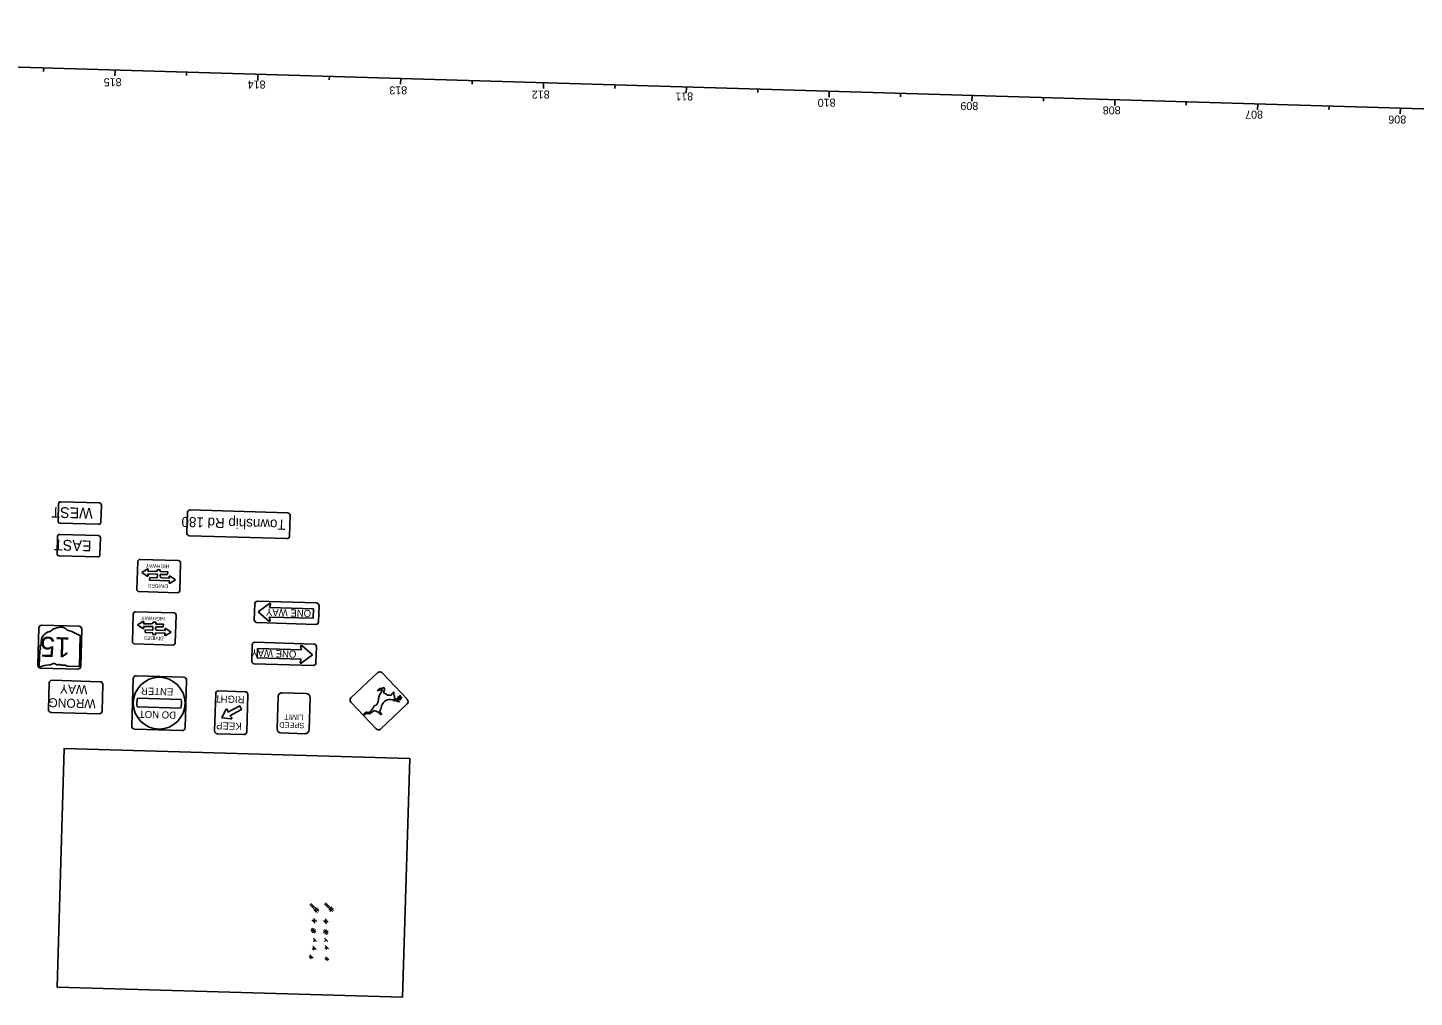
# Model space of a CAD drawing. Extents: x 1658454 to 1663955, y 480219 to 484109.
# Drawn here: x 1659392 to 1660362, y 482120 to 482799 of the extents above; entities that cross this region are included whole.
import ezdxf

# ---------------------------------------------------------------- set-up
doc = ezdxf.new("R2010")
doc.units = 0
for name, color, linetype in [('Default', 7, 'Continuous'), ('SN_P_Signs', 7, 'Continuous'), ('SN_X_Public', 7, 'Continuous'), ('SV_X_CL_Survey_50', 7, 'Continuous'), ('SV_X_Text', 7, 'Continuous')]:
    doc.layers.add(name, color=color, linetype=linetype)

msp = doc.modelspace()

# ---------------------------------------------------------------- linework, layer by layer
at = {"layer": 'Default'}
for p, q in [((1659403.25, 482770.68), (1659403.18, 482768.28)), ((1659453.23, 482769.19), (1659453.11, 482765.19)), ((1659503.2, 482767.71), (1659503.13, 482765.31)), ((1659553.18, 482766.23), (1659553.06, 482762.23)), ((1659603.16, 482764.74), (1659603.09, 482762.34)), ((1659653.14, 482763.26), (1659653.02, 482759.26)), ((1659703.12, 482761.77), (1659703.04, 482759.37)), ((1659753.09, 482760.29), (1659752.97, 482756.29)), ((1659803.07, 482758.81), (1659803, 482756.41)), ((1659853.05, 482757.32), (1659852.93, 482753.32)), ((1659903.03, 482755.84), (1659902.96, 482753.44)), ((1659953.01, 482754.35), (1659952.89, 482750.36)), ((1660002.98, 482752.87), (1660002.91, 482750.47)), ((1660052.96, 482751.39), (1660052.84, 482747.39)), ((1660102.94, 482749.9), (1660102.87, 482747.5)), ((1660152.92, 482748.42), (1660152.8, 482744.42)), ((1660202.89, 482746.93), (1660202.82, 482744.54)), ((1660252.87, 482745.45), (1660252.75, 482741.45)), ((1660302.85, 482743.97), (1660302.78, 482741.57)), ((1660352.83, 482742.48), (1660352.71, 482738.48))]:
    msp.add_line(p, q, dxfattribs=at)
at = {"layer": 'SN_P_Signs'}
for p, q in [((1659594.96, 482179.5), (1659589.53, 482184.93)), ((1659595.67, 482180.21), (1659590.23, 482185.64)), ((1659591.59, 482184.28), (1659590.89, 482183.57)), ((1659594.66, 482182.76), (1659592.4, 482180.5)), ((1659592.6, 482182.57), (1659592.6, 482182.57)), ((1659595.51, 482181.92), (1659593.25, 482179.65)), ((1659593.16, 482171.88), (1659590.89, 482174.15)), ((1659591.68, 482173.36), (1659592.82, 482174.49)), ((1659594.29, 482173.02), (1659592.02, 482175.28)), ((1659592.36, 482172.68), (1659593.5, 482173.81)), ((1659592.59, 482173.58), (1659592.59, 482173.58)), ((1659592.89, 482164.99), (1659590.17, 482167.7)), ((1659592.59, 482168.25), (1659590.33, 482165.99)), ((1659593.6, 482165.69), (1659590.88, 482168.41)), ((1659593.44, 482167.4), (1659591.18, 482165.14)), ((1659591.88, 482166.7), (1659591.88, 482166.7)), ((1659592.35, 482154.96), (1659591.22, 482153.83)), ((1659591.56, 482155.75), (1659593.82, 482153.49)), ((1659593.03, 482154.28), (1659591.9, 482153.15)), ((1659591.94, 482161.42), (1659594.2, 482159.16)), ((1659593.07, 482160.29), (1659591.94, 482159.16)), ((1659592.69, 482154.62), (1659592.69, 482154.62)), ((1659592.69, 482154.62), (1659592.69, 482154.62)), ((1659590.17, 482149.17), (1659589.04, 482148.04)), ((1659589.55, 482149.79), (1659591.81, 482147.53)), ((1659590.68, 482148.66), (1659589.55, 482147.53)), ((1659591.19, 482148.15), (1659590.06, 482147.02))]:
    msp.add_line(p, q, dxfattribs=at)
at = {"layer": 'SN_X_Public'}
for p, q in [((1659413.24, 482453.53), (1659413.59, 482465.52)), ((1659415.14, 482466.97), (1659442.12, 482466.17)), ((1659443.58, 482464.63), (1659443.22, 482452.63)), ((1659503.34, 482445.2), (1659503.76, 482459.36)), ((1659505.74, 482461.22), (1659573.87, 482459.2)), ((1659575.74, 482457.22), (1659575.31, 482443.07)), ((1659414.46, 482444.14), (1659441.45, 482443.34)), ((1659441.68, 482451.18), (1659414.69, 482451.98)), ((1659412.56, 482430.69), (1659412.91, 482442.69)), ((1659442.9, 482441.8), (1659442.54, 482429.8)), ((1659573.34, 482441.2), (1659505.2, 482443.23)), ((1659441, 482428.35), (1659414.01, 482429.15)), ((1659468.98, 482425.13), (1659468.41, 482405.64)), ((1659497.52, 482425.78), (1659470.53, 482426.58)), ((1659498.39, 482404.75), (1659498.97, 482424.24)), ((1659475.73, 482419.83), (1659471.89, 482417.47)), ((1659471.89, 482417.47), (1659475.59, 482414.88)), ((1659476.3, 482415.36), (1659476.03, 482416.41)), ((1659476.03, 482416.41), (1659482.79, 482416.21)), ((1659476.1, 482418.28), (1659476.42, 482419.31)), ((1659481.6, 482418.12), (1659476.1, 482418.28)), ((1659482.79, 482416.21), (1659482.71, 482413.71)), ((1659484.76, 482419.28), (1659482.88, 482419.33)), ((1659482.88, 482419.33), (1659482.88, 482419.33)), ((1659484.63, 482414.9), (1659484.66, 482416.15)), ((1659484.66, 482416.15), (1659489.97, 482416)), ((1659484.72, 482418.03), (1659484.76, 482419.28)), ((1659490.03, 482417.87), (1659484.72, 482418.03)), ((1659489.97, 482416), (1659490.03, 482417.87)), ((1659491.1, 482414.5), (1659491.35, 482413.45)), ((1659495.49, 482412.39), (1659491.79, 482414.98)), ((1659477.41, 482413.87), (1659477.35, 482411.99)), ((1659477.35, 482411.99), (1659491.3, 482411.58)), ((1659482.71, 482413.71), (1659477.41, 482413.87)), ((1659491.35, 482413.45), (1659485.84, 482413.62)), ((1659491.3, 482411.58), (1659490.99, 482410.57)), ((1659491.65, 482410.03), (1659495.49, 482412.39)), ((1659491.65, 482410.04), (1659491.65, 482410.03)), ((1659469.86, 482404.09), (1659496.85, 482403.29)), ((1659553.27, 482389.81), (1659561.25, 482395.72)), ((1659561.98, 482395.21), (1659561.29, 482392.84)), ((1659465.33, 482368.97), (1659465.91, 482388.46)), ((1659467.45, 482389.91), (1659494.44, 482389.11)), ((1659495.9, 482387.57), (1659495.32, 482368.08)), ((1659560.88, 482383.41), (1659553.27, 482389.81)), ((1659591.92, 482385.37), (1659561.1, 482386.28)), ((1659561.1, 482386.28), (1659561.65, 482383.87)), ((1659561.29, 482392.84), (1659592.11, 482391.93)), ((1659592.11, 482391.93), (1659591.92, 482385.37)), ((1659472.66, 482383.16), (1659468.81, 482380.8)), ((1659468.81, 482380.8), (1659472.51, 482378.22)), ((1659473.23, 482378.69), (1659472.96, 482379.74)), ((1659472.96, 482379.74), (1659479.71, 482379.54)), ((1659473.02, 482381.61), (1659473.34, 482382.64)), ((1659478.52, 482381.45), (1659473.02, 482381.61)), ((1659474.33, 482377.2), (1659474.28, 482375.32)), ((1659479.64, 482377.04), (1659474.33, 482377.2)), ((1659479.71, 482379.54), (1659479.64, 482377.04)), ((1659481.68, 482382.61), (1659479.81, 482382.66)), ((1659479.81, 482382.66), (1659479.81, 482382.66)), ((1659481.55, 482378.23), (1659481.59, 482379.48)), ((1659481.59, 482379.48), (1659486.9, 482379.33)), ((1659481.64, 482381.36), (1659481.68, 482382.61)), ((1659486.95, 482381.2), (1659481.64, 482381.36)), ((1659488.28, 482376.78), (1659482.76, 482376.95)), ((1659486.9, 482379.33), (1659486.95, 482381.2)), ((1659488.03, 482377.83), (1659488.28, 482376.78)), ((1659488.57, 482373.36), (1659492.42, 482375.72)), ((1659492.42, 482375.72), (1659488.72, 482378.31)), ((1659428.19, 482351.9), (1659428.83, 482373.24)), ((1659493.77, 482366.62), (1659466.79, 482367.42)), ((1659474.28, 482375.32), (1659479.58, 482375.16)), ((1659479.58, 482375.16), (1659479.55, 482373.92)), ((1659479.55, 482373.92), (1659481.42, 482373.86)), ((1659481.42, 482373.86), (1659481.46, 482375.11)), ((1659481.46, 482375.11), (1659488.23, 482374.91)), ((1659488.23, 482374.91), (1659487.91, 482373.9)), ((1659488.58, 482373.37), (1659488.57, 482373.36)), ((1659583.06, 482365.78), (1659583.6, 482363.37)), ((1659591.43, 482359.86), (1659583.82, 482366.24)), ((1659400.39, 482363), (1659400.06, 482351.84)), ((1659400.39, 482363), (1659400.39, 482363)), ((1659552.78, 482364.28), (1659552.59, 482357.72)), ((1659552.59, 482357.72), (1659583.41, 482356.81)), ((1659583.6, 482363.37), (1659552.78, 482364.28)), ((1659583.41, 482356.81), (1659582.72, 482354.43)), ((1659583.45, 482353.92), (1659591.43, 482359.86)), ((1659419.67, 482351.79), (1659427.91, 482351.54)), ((1659468.82, 482329.53), (1659499.42, 482328.62)), ((1659647.76, 482328.4), (1659646, 482328.54)), ((1659646.01, 482331.45), (1659646.72, 482331.65)), ((1659499.24, 482322.38), (1659468.63, 482323.29)), ((1659527.86, 482315.71), (1659530.77, 482321.51)), ((1659531.79, 482321.37), (1659532.13, 482319.61)), ((1659532.13, 482319.61), (1659540.4, 482324.06)), ((1659541.73, 482321.58), (1659533.46, 482317.13)), ((1659540.4, 482324.06), (1659541.73, 482321.58)), ((1659534.3, 482314.95), (1659527.86, 482315.71)), ((1659533.46, 482317.13), (1659534.75, 482315.88)), ((1659605.23, 482180), (1659599.8, 482185.43)), ((1659605.94, 482180.71), (1659600.51, 482186.14)), ((1659601.86, 482184.78), (1659601.16, 482184.07)), ((1659604.93, 482183.27), (1659602.67, 482181)), ((1659602.87, 482183.07), (1659602.87, 482183.07)), ((1659605.78, 482182.42), (1659603.52, 482180.15)), ((1659601.23, 482171.51), (1659598.97, 482173.77)), ((1659599.76, 482172.98), (1659600.89, 482174.11)), ((1659602.36, 482172.64), (1659600.1, 482174.9)), ((1659600.44, 482172.3), (1659601.57, 482173.43)), ((1659600.66, 482173.21), (1659600.66, 482173.21)), ((1659601.69, 482164.08), (1659598.98, 482166.79)), ((1659601.39, 482167.34), (1659599.13, 482165.08)), ((1659602.4, 482164.78), (1659599.68, 482167.5)), ((1659602.24, 482166.5), (1659599.98, 482164.23)), ((1659600.69, 482165.79), (1659600.69, 482165.79)), ((1659599.79, 482161.32), (1659602.06, 482159.06)), ((1659600.93, 482160.19), (1659599.79, 482159.06)), ((1659601.08, 482155.39), (1659599.95, 482154.26)), ((1659600.29, 482156.18), (1659602.55, 482153.92)), ((1659601.76, 482154.71), (1659600.63, 482153.58)), ((1659601.42, 482155.05), (1659601.42, 482155.05)), ((1659601.19, 482147.82), (1659600.06, 482146.69)), ((1659600.57, 482148.44), (1659602.83, 482146.18)), ((1659601.7, 482147.31), (1659600.57, 482146.18)), ((1659602.21, 482146.8), (1659601.08, 482145.67))]:
    msp.add_line(p, q, dxfattribs=at)
for points in [[(1659550.95, 482395.49), (1659550.62, 482384.25)], [(1659594.11, 482396.09), (1659552.88, 482397.31)], [(1659595.6, 482382.91), (1659595.93, 482394.16)], [(1659399.89, 482378.72), (1659399.12, 482352.48)], [(1659428.06, 482379.76), (1659401.82, 482380.54)], [(1659429.1, 482351.59), (1659429.88, 482377.83)], [(1659552.44, 482382.32), (1659593.67, 482381.09)], [(1659548.77, 482355.49), (1659549.1, 482366.74)], [(1659551.03, 482368.56), (1659592.27, 482367.33)], [(1659594.09, 482365.4), (1659593.75, 482354.16)], [(1659400.93, 482350.55), (1659427.17, 482349.77)], [(1659591.82, 482352.34), (1659550.59, 482353.56)], [(1659618.28, 482329.65), (1659637.06, 482347.34)], [(1659640.03, 482347.26), (1659657.72, 482328.48)], [(1659407.11, 482340.15), (1659406.55, 482321.41)], [(1659442.78, 482340.97), (1659409.04, 482341.97)], [(1659444.04, 482320.3), (1659444.59, 482339.04)], [(1659465.77, 482342.91), (1659464.8, 482310.11)], [(1659500.98, 482344.21), (1659468.18, 482345.18)], [(1659502.28, 482309), (1659503.25, 482341.8)], [(1659637.59, 482334.51), (1659636.78, 482334.71), (1659636.97, 482335.09), (1659638.33, 482336.18), (1659639.76, 482336.13), (1659640.85, 482336.77)], [(1659522.83, 482306.48), (1659523.61, 482332.72)], [(1659525.54, 482334.54), (1659544.28, 482333.98)], [(1659546.1, 482332.05), (1659545.32, 482305.81)], [(1659567.23, 482330.49), (1659566.56, 482308)], [(1659586.99, 482332.71), (1659570.12, 482333.22)], [(1659589.05, 482307.33), (1659589.72, 482329.82)], [(1659639.86, 482335.25), (1659639.38, 482335.2), (1659638.69, 482335.18)], [(1659641.51, 482332.9), (1659642.66, 482332.52), (1659643.93, 482331.64)], [(1659648.63, 482327.43), (1659648.49, 482327.62), (1659647.68, 482328.14), (1659647.76, 482328.4), (1659647.76, 482328.4)], [(1659408.37, 482319.48), (1659442.11, 482318.48)], [(1659635.89, 482307.9), (1659618.19, 482326.68)], [(1659631.05, 482318.6), (1659628.55, 482318.67), (1659628.22, 482317.99), (1659627.28, 482318.02), (1659628.26, 482319.19)], [(1659657.63, 482325.51), (1659638.86, 482307.82)], [(1659467.07, 482307.7), (1659499.87, 482306.73)], [(1659543.39, 482304), (1659524.65, 482304.55)], [(1659569.29, 482305.1), (1659586.15, 482304.6)]]:
    msp.add_lwpolyline(points, dxfattribs=at)
msp.add_circle((1659484.03, 482325.95), 18.12, dxfattribs=at)
for centre, radius, start, end in [((1659415.09, 482465.48), 1.5, 88.29934, 178.29934), ((1659442.08, 482464.67), 1.5, 358.29934, 88.29934), ((1659414.74, 482453.48), 1.5, 178.29934, 268.29934), ((1659505.68, 482459.3), 1.92, 88.29934, 178.29934), ((1659573.82, 482457.28), 1.92, 358.29934, 88.29934), ((1659414.41, 482442.65), 1.5, 88.29934, 178.29934), ((1659441.72, 482452.68), 1.5, 268.29934, 358.29934), ((1659505.26, 482445.15), 1.92, 178.29934, 268.29934), ((1659441.4, 482441.84), 1.5, 358.29934, 88.29934), ((1659573.4, 482443.12), 1.92, 268.29934, 358.29934), ((1659414.06, 482430.65), 1.5, 178.29934, 268.29934), ((1659441.05, 482429.85), 1.5, 268.29934, 358.29934), ((1659470.49, 482425.08), 1.5, 88.29934, 178.29934), ((1659497.47, 482424.28), 1.5, 358.29934, 88.29934), ((1659475.85, 482415.26), 0.458, 235.0597, 13.92632), ((1659475.97, 482419.44), 0.458, 342.67236, 121.53898), ((1659481.64, 482419.37), 1.25, 268.29934, 358.29934), ((1659485.87, 482414.86), 1.25, 178.29934, 268.29934), ((1659491.54, 482414.61), 0.458, 55.0597, 193.92632), ((1659469.91, 482405.59), 1.5, 178.29934, 268.29934), ((1659491.41, 482410.43), 0.458, 162.67236, 301.53898), ((1659496.89, 482404.79), 1.5, 268.29934, 358.29934), ((1659552.83, 482395.44), 1.87, 88.29934, 178.29934), ((1659561.53, 482395.34), 0.471, 344.05613, 126.67187), ((1659594.06, 482394.21), 1.87, 358.29934, 88.29934), ((1659467.41, 482388.41), 1.5, 88.29934, 178.29934), ((1659494.4, 482387.61), 1.5, 358.29934, 88.29934), ((1659401.77, 482378.66), 1.88, 88.29934, 178.29934), ((1659408.91, 482368.85), 7.46, 110.60823, 187.28518), ((1659406.09, 482379.91), 4.09, 272.70246, 320.87609), ((1659411.15, 482375.83), 2.41, 101.17253, 141.57645), ((1659410.97, 482378.78), 0.641, 244.05107, 310.94776), ((1659412.96, 482376.65), 2.28, 87.07636, 133.84861), ((1659413.45, 482382.42), 3.51, 263.99446, 289.50929), ((1659415.7, 482374.97), 4.28, 48.99971, 104.59118), ((1659423.23, 482383), 6.74, 225.4835, 254.13531), ((1659415.99, 482355.67), 21.54, 58.71226, 75.49784), ((1659428.01, 482377.88), 1.88, 358.29934, 88.29934), ((1659472.77, 482378.59), 0.458, 235.0597, 13.92632), ((1659472.9, 482382.77), 0.458, 342.67236, 121.53898), ((1659478.56, 482382.7), 1.25, 268.29934, 358.29934), ((1659482.8, 482378.19), 1.25, 178.29934, 268.29934), ((1659488.46, 482377.94), 0.458, 55.0597, 193.92632), ((1659552.49, 482384.19), 1.87, 178.29934, 268.29934), ((1659561.19, 482383.77), 0.471, 229.95732, 12.51673), ((1659593.72, 482382.97), 1.87, 268.29934, 358.29934), ((1659403.61, 482365.14), 2.91, 158.3323, 201.94891), ((1659399.4, 482367.71), 2.12, 315.10584, 5.22893), ((1659427.98, 482374.5), 0.905, 208.04772, 271.57109), ((1659428.39, 482371.11), 2.51, 85.63833, 98.9032), ((1659428.5, 482373.3), 0.329, 350.25773, 76.60595), ((1659466.83, 482368.92), 1.5, 178.29934, 268.29934), ((1659488.34, 482373.76), 0.458, 162.67236, 301.53898), ((1659493.82, 482368.12), 1.5, 268.29934, 358.29934), ((1659550.98, 482366.68), 1.87, 88.29934, 178.29934), ((1659583.52, 482365.88), 0.471, 49.92681, 192.54255), ((1659592.21, 482365.46), 1.87, 358.29934, 88.29934), ((1659400.72, 482363.04), 0.335, 107.90315, 186.03347), ((1659400.48, 482363.82), 0.485, 286.24332, 28.63631), ((1659400.99, 482352.42), 1.88, 178.29934, 268.29934), ((1659400.37, 482351.79), 0.313, 170.16143, 276.03734), ((1659409.22, 482322.98), 29.83, 94.14381, 107.20579), ((1659406.48, 482358.7), 6, 275.64552, 299.06819), ((1659410.29, 482351.36), 2.28, 52.15555, 113.12753), ((1659412.83, 482354.67), 1.9, 232.76602, 297.44047), ((1659414.1, 482352.17), 0.912, 38.0914, 115.40171), ((1659417.02, 482363.86), 11.35, 258.78603, 273.28761), ((1659417.64, 482349.37), 3.16, 49.91885, 89.41122), ((1659427.23, 482351.64), 1.88, 268.29934, 358.29934), ((1659427.87, 482351.87), 0.326, 276.42944, 6.42944), ((1659550.65, 482355.44), 1.87, 178.29934, 268.29934), ((1659583.17, 482354.3), 0.471, 164.08195, 306.64136), ((1659591.88, 482354.21), 1.87, 268.29934, 358.29934), ((1659638.5, 482345.81), 2.1, 43.29934, 133.29934), ((1659408.98, 482340.1), 1.87, 88.29934, 178.29934), ((1659442.72, 482339.1), 1.87, 358.29934, 88.29934), ((1659468.11, 482342.84), 2.34, 88.29934, 178.29934), ((1659500.91, 482341.87), 2.34, 358.29934, 88.29934), ((1659641.15, 482336.26), 0.593, 2.63463, 120.19731), ((1659484.03, 482325.95), 15.62, 166.76238, 189.8363), ((1659484.03, 482325.95), 15.62, 346.76238, 9.8363), ((1659525.48, 482332.66), 1.87, 88.29934, 178.29934), ((1659544.22, 482332.11), 1.87, 358.29934, 88.29934), ((1659570.04, 482330.4), 2.81, 88.29934, 178.29934), ((1659586.91, 482329.9), 2.81, 358.29934, 88.29934), ((1659619.72, 482328.12), 2.1, 133.29934, 223.29934), ((1659628.82, 482329.73), 8.84, 328.01516, 357.51473), ((1659638.72, 482333.9), 1.28, 91.2294, 151.83119), ((1659643.33, 482329.1), 5.68, 147.98842, 177.51473), ((1659618.43, 482344.67), 23.69, 327.98842, 335.71139), ((1659645.81, 482322.34), 6.32, 130.64019, 164.35622), ((1659639.94, 482335.21), 0.0933, 20.88729, 155.71139), ((1659639.64, 482335.1), 0.413, 335.71139, 20.88729), ((1659642.66, 482333.31), 1.5, 169.5087, 187.08998), ((1659641.44, 482333.16), 0.265, 187.08998, 286.39166), ((1659649.25, 482332.09), 8.2, 160.37674, 169.5087), ((1659637.97, 482336.11), 3.77, 340.37674, 2.63463), ((1659645.54, 482322.66), 5.9, 85.48239, 130.64019), ((1659644.58, 482327.21), 4.47, 71.32687, 98.40328), ((1659648.58, 482331.67), 1.86, 123.54589, 180.45104), ((1659647.72, 482332.97), 0.304, 68.59738, 123.54589), ((1659649.82, 482331.64), 2.56, 133.2682, 141.14025), ((1659648.21, 482333.36), 0.208, 29.98489, 133.2682), ((1659651.4, 482332.52), 3.16, 162.61939, 208.96231), ((1659648.63, 482328.37), 0.0793, 70.11299, 252.53377), ((1659647.83, 482327.84), 0.902, 332.40863, 30.2681), ((1659654.7, 482330.45), 6.08, 174.86266, 191.04392), ((1659647.29, 482324.67), 4.02, 52.27544, 70.11299), ((1659649.75, 482330.02), 1.26, 215.889, 320.70968), ((1659652.4, 482331.27), 4.32, 232.27544, 253.45969), ((1659608.91, 482363.43), 54.02, 320.70968, 322.266), ((1659651.22, 482327.85), 0.38, 116.06447, 232.31736), ((1659651.63, 482328.37), 1.04, 232.31736, 285.67774), ((1659652.24, 482327.09), 1.61, 64.85983, 137.12241), ((1659651.63, 482327.78), 0.803, 234.85898, 290.04994), ((1659652.91, 482329.77), 1.42, 79.03378, 154.83056), ((1659651.91, 482329.19), 0.134, 124.26495, 320.99305), ((1659653.14, 482327.39), 2.32, 74.92516, 124.26495), ((1659651.96, 482327.19), 0.179, 250.92094, 105.67774), ((1659652.4, 482330.19), 0.43, 99.0122, 198.23396), ((1659651.84, 482336.05), 5.99, 271.42436, 279.91), ((1659652.03, 482327.47), 1.63, 50.5294, 90.53258), ((1659652.14, 482331.86), 1.26, 279.0122, 326.20978), ((1659653.07, 482329.04), 1.12, 52.36495, 99.91), ((1659652.99, 482328.64), 0.117, 233.61235, 50.5294), ((1659653.63, 482329.78), 0.187, 304.23373, 52.36495), ((1659656.19, 482327.04), 2.1, 313.29934, 43.29934), ((1659408.43, 482321.36), 1.87, 178.29934, 268.29934), ((1659442.16, 482320.35), 1.87, 268.29934, 358.29934), ((1659531.26, 482321.27), 0.547, 10.66154, 153.37858), ((1659629.15, 482318.44), 1.17, 77.26592, 140.16796), ((1659630.05, 482322.41), 2.9, 257.26592, 319.33316), ((1659630.49, 482321.2), 2.67, 281.92633, 307.00815), ((1659582.45, 482384.94), 82.48, 307.00815, 308.22151), ((1659616.33, 482334.19), 20.99, 319.33316, 325.64071), ((1659634.94, 482318.29), 2.35, 45.24982, 128.22151), ((1659632.15, 482323.37), 1.82, 325.64071, 349.33227), ((1659635.42, 482322.76), 1.5, 100.6889, 169.33226), ((1659634.8, 482326), 1.79, 280.6889, 328.01516), ((1659637.17, 482320.54), 0.812, 225.24982, 326.89345), ((1659641.15, 482320.34), 3.31, 184.18543, 214.58719), ((1659639.17, 482318.98), 0.912, 214.58719, 325.97364), ((1659634.19, 482323.49), 5.27, 324.41086, 349.41533), ((1659642.73, 482320.73), 4.26, 184.22664, 204.53147), ((1659641.97, 482324.35), 6.23, 239.89954, 250.86955), ((1659656.83, 482319.26), 17.77, 164.35622, 169.41533), ((1659467.14, 482310.04), 2.34, 178.29934, 268.29934), ((1659499.94, 482309.07), 2.34, 268.29934, 358.29934), ((1659534.37, 482315.49), 0.547, 263.2201, 45.93714), ((1659569.37, 482307.91), 2.81, 178.29934, 268.29934), ((1659637.42, 482309.34), 2.1, 223.29934, 313.29934), ((1659524.7, 482306.43), 1.87, 178.29934, 268.29934), ((1659543.44, 482305.87), 1.87, 268.29934, 358.29934), ((1659586.24, 482307.41), 2.81, 268.29934, 358.29934)]:
    msp.add_arc(centre, radius, start, end, dxfattribs=at)
at = {"layer": 'SV_X_CL_Survey_50'}
msp.add_line((1663951.73, 482635.63), (1658453.66, 482798.87), dxfattribs=at)
msp.add_lwpolyline([(1659654.44, 482120.03), (1659412.55, 482127.21), (1659417.51, 482294.3), (1659659.4, 482287.11)], close=True, dxfattribs=at)

# ---------------------------------------------------------------- texts
at = {"layer": 'SN_X_Public'}
for s, height, p in [('WEST', 7.5, (1659437.63, 482462.56)), ('Township Rd 180', 7.0009, (1659572.59, 482454.26)), ('EAST', 7.5, (1659436.74, 482439.73)), ('HIGHWAY', 2.5, (1659491.12, 482422.84)), ('DIVIDED', 2.5, (1659490.22, 482409.12)), ('HIGHWAY', 2.5, (1659488.05, 482386.17)), ('ONE WAY', 5, (1659590.42, 482391.2)), ('15', 14.063, (1659421.84, 482371.94)), ('DIVIDED', 2.5, (1659487.15, 482372.45)), ('ONE WAY', 5, (1659580.14, 482362.69)), ('WAY', 6.281, (1659433.83, 482338.44)), ('ENTER', 5, (1659493.98, 482336.29)), ('WRONG', 6.281, (1659439.72, 482328.51)), ('RIGHT', 5, (1659543.84, 482330.87)), ('DO NOT', 5, (1659495.9, 482319.97)), ('LIMIT', 3.751, (1659584.91, 482317.77)), ('KEEP', 5, (1659541.83, 482312.17)), ('SPEED', 3.751, (1659585.66, 482312.12))]:
    msp.add_text(s, height=height, rotation=178.29934, dxfattribs=at).set_placement(p)
at = {"layer": 'SV_X_Text'}
for s, p in [('815', (1659457.67, 482763.57)), ('814', (1659558.45, 482761.9)), ('813', (1659657.57, 482757.88)), ('812', (1659757.31, 482754.92)), ('811', (1659857.69, 482753.57)), ('810', (1659957.39, 482749.23)), ('809', (1660057.29, 482746.89)), ('808', (1660156.92, 482743.89)), ('807', (1660256.55, 482740.85)), ('806', (1660356.8, 482737.44))]:
    msp.add_text(s, height=5.6, rotation=180.53411, dxfattribs=at).set_placement(p)

doc.saveas('drawing.dxf')
